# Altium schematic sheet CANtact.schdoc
size 366 x 256 mm
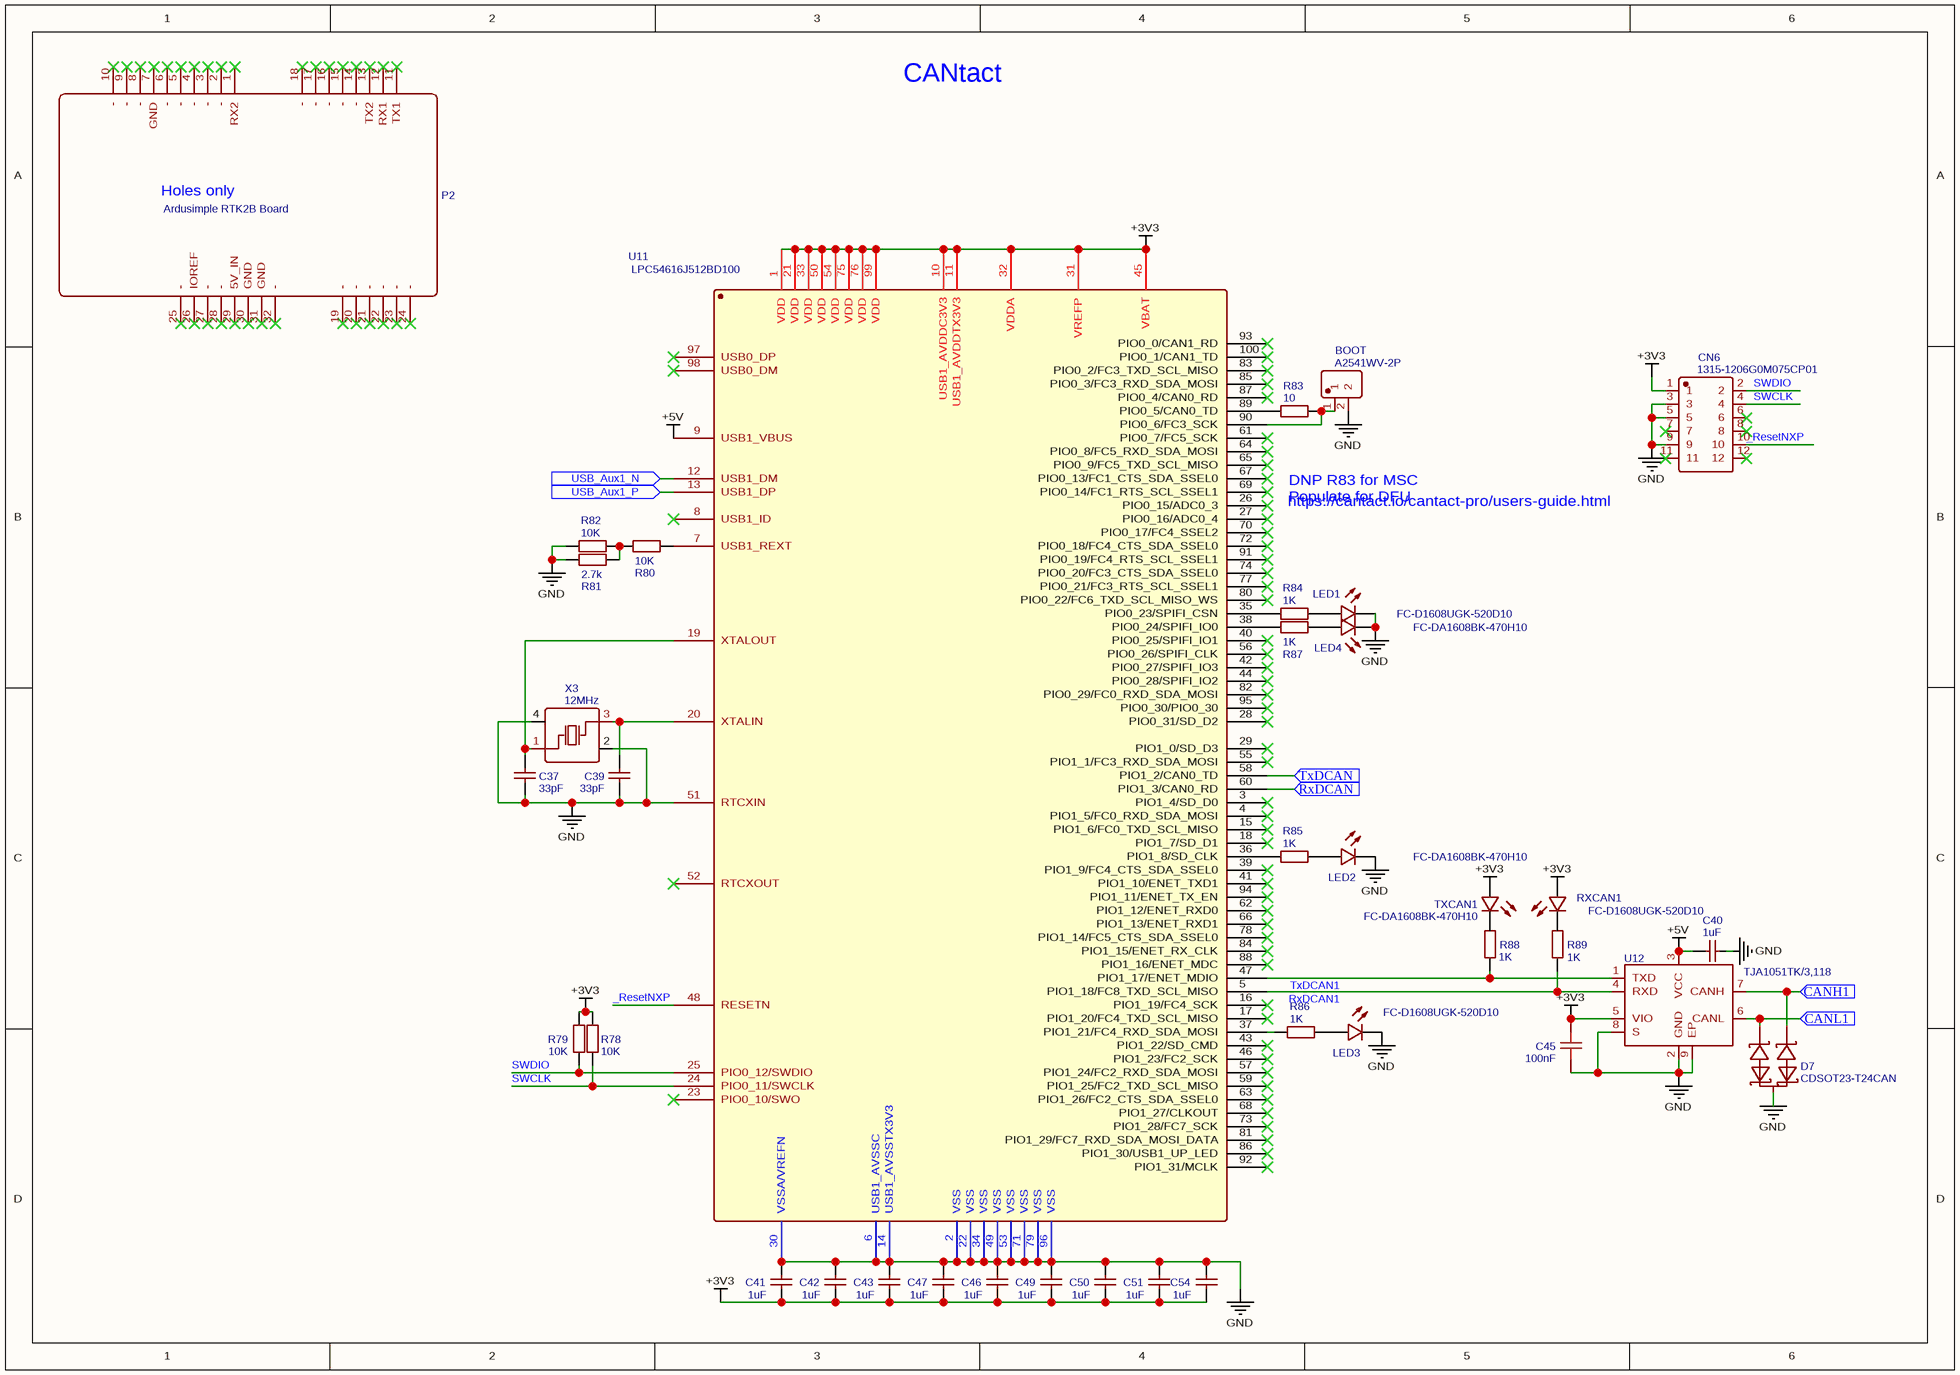
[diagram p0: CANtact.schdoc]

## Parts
BOOT  A2541WV-2P  [HDR-TH_P2.54-H-M_A2541WV-2P]
C37  33pF  [C0603]
C39  33pF  [C0603]
C40  1uF  [C0603]
C41  1uF  [C0603]
C42  1uF  [C0603]
C43  1uF  [C0603]
C45  100nF  [C0603]
C46  1uF  [C0603]
C47  1uF  [C0603]
C49  1uF  [C0603]
C50  1uF  [C0603]
C51  1uF  [C0603]
C54  1uF  [C0603]
CN6  1315-1206G0M075CP01  [HDR-SMD_12P-P1.27-V-M-R2-C6-S7.50]
D7  CDSOT23-T24CAN  [SOT-23_L2.9-W1.3-P0.95-LS2.4-BR]
LED1  FC-D1608UGK-520D10  [LED0603-RD]
LED2  FC-DA1608BK-470H10  [LED0603-RD]
LED3  FC-D1608UGK-520D10  [LED0603-RD]
LED4  FC-DA1608BK-470H10  [LED0603-RD]
P2  Ardusimple RTK2B Board  [ARDUSIMPLE_MECH]
R78  10K  [R0603]
R79  10K  [R0603]
R80  10K  [R0603]
R81  2.7k  [R0603]
R82  10K  [R0603]
R83  10  [R0603]
R84  1K  [R0603]
R85  1K  [R0603]
R86  1K  [R0603]
R87  1K  [R0603]
R88  1K  [R0603]
R89  1K  [R0603]
RXCAN1  FC-D1608UGK-520D10  [LED0603-RD]
TXCAN1  FC-DA1608BK-470H10  [LED0603-RD]
U11  LPC54616J512BD100  [TQFP-100_14X14X05P]
U12  TJA1051TK/3,118  [HVSON-8_L3.0-W3.0-P0.65-BL-EP]
X3  12MHz  [OSC-SMD_4P-L3.2-W2.5-BL]

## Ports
CANH1 (in), CANL1 (in), RxDCAN (in), TxDCAN (in), USB_Aux1_N (in), USB_Aux1_P (in)

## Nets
+3V3: C41.2 C42.2 C43.2 C45.2 C46.2 C47.2 C49.2 C50.2 C51.2 C54.2 CN6.1 R78.1 R79.1 RXCAN1.2(A) TXCAN1.2(+) U11.1(VDD) U11.10(USB1_AVDDC3V3) U11.11(USB1_AVDDTX3V3) U11.21(VDD) U11.31(VREFP) U11.32(VDDA) U11.33(VDD) U11.45(VBAT) U11.50(VDD) U11.54(VDD) U11.75(VDD) U11.76(VDD) U11.99(VDD) U12.5(VIO)
+5V: C40.1 U11.9(USB1_VBUS) U12.3(VCC)
GND: BOOT.2 C37.1 C39.1 C40.2 C41.1 C42.1 C43.1 C45.1 C46.1 C47.1 C49.1 C50.1 C51.1 C54.1 CN6.3 CN6.5 CN6.9 D7.3 LED1.1(K) LED2.1(-) LED3.1(K) LED4.1(-) R81.2 R82.2 U11.2(VSS) U11.6(USB1_AVSSC) U11.14(USB1_AVSSTX3V3) U11.22(VSS) U11.30(VSSA/VREFN) U11.34(VSS) U11.49(VSS) U11.51(RTCXIN) U11.53(VSS) U11.71(VSS) U11.79(VSS) U11.96(VSS) U12.2(GND) U12.8(S) U12.9(EP) X3.2(GND) X3.4(GND)
_ResetNXP: CN6.10 U11.48(RESETN)
CANH1: D7.1 U12.7(CANH) ; port CANH1
CANL1: D7.2 U12.6(CANL) ; port CANL1
RxDCAN: U11.60(PIO1_3/CAN0_RD) ; port RxDCAN
RxDCAN1: R89.2 U11.5(PIO1_18/FC8_TXD_SCL_MISO) U12.4(RXD)
SWCLK: CN6.4 R78.2 U11.24(PIO0_11/SWCLK)
SWDIO: CN6.2 R79.2 U11.25(PIO0_12/SWDIO)
TxDCAN: U11.58(PIO1_2/CAN0_TD) ; port TxDCAN
TxDCAN1: R88.2 U11.47(PIO1_17/ENET_MDIO) U12.1(TXD)
USB_Aux1_N: U11.12(USB1_DM) ; port USB_Aux1_N
USB_Aux1_P: U11.13(USB1_DP) ; port USB_Aux1_P
NetBOOT_1: BOOT.1 R83.1 U11.90(PIO0_6/FC3_SCK)
NetC37_2: C37.2 U11.19(XTALOUT) X3.1(OSC1)
NetC39_2: C39.2 U11.20(XTALIN) X3.3(OSC2)
NetLED1_2: LED1.2(A) R84.1
NetLED2_2: LED2.2(+) R85.1
NetLED3_2: LED3.2(A) R86.1
NetLED4_2: LED4.2(+) R87.1
NetR80_1: R80.1 U11.7(USB1_REXT)
NetR80_2: R80.2 R81.1 R82.1
NetR83_2: R83.2 U11.89(PIO0_5/CAN0_TD)
NetR84_2: R84.2 U11.35(PIO0_23/SPIFI_CSN)
NetR85_2: R85.2 U11.36(PIO1_8/SD_CLK)
NetR86_2: R86.2 U11.37(PIO1_21/FC4_RXD_SDA_MOSI)
NetR87_2: R87.2 U11.38(PIO0_24/SPIFI_IO0)
NetR88_1: R88.1 TXCAN1.1(-)
NetR89_1: R89.1 RXCAN1.1(K)

Not connected (* = marked no-connect by the designer): CN6 6* 7* 8* 11* 12*; P2 1(RX2)* 2(-)* 3(-)* 4(-)* 5(-)* 6(-)* 7(GND)* 8(-)* 9(-)* 10(-)* 11(TX1)* 12(RX1)* 13(TX2)* 14(-)* 15(-)* 16(-)* 17(-)* 18(-)* 19(-)* 20(-)* 21(-)* 22(-)* 23(-)* 24(-)* 25(-)* 26(IOREF)* 27(-)* 28(-)* 29(5V_IN)* 30(GND)* 31(GND)* 32(-)*; U11 3(PIO1_4/SD_D0)* 4(PIO1_5/FC0_RXD_SDA_MOSI)* 8(USB1_ID)* 15(PIO1_6/FC0_TXD_SCL_MISO)* 16(PIO1_19/FC4_SCK)* 17(PIO1_20/FC4_TXD_SCL_MISO)* 18(PIO1_7/SD_D1)* 23(PIO0_10/SWO)* 26(PIO0_15/ADC0_3)* 27(PIO0_16/ADC0_4)* 28(PIO0_31/SD_D2)* 29(PIO1_0/SD_D3)* 39(PIO1_9/FC4_CTS_SDA_SSEL0)* 40(PIO0_25/SPIFI_IO1)* 41(PIO1_10/ENET_TXD1)* 42(PIO0_27/SPIFI_IO3)* 43(PIO1_22/SD_CMD)* 44(PIO0_28/SPIFI_IO2)* 46(PIO1_23/FC2_SCK)* 52(RTCXOUT)* 55(PIO1_1/FC3_RXD_SDA_MOSI)* 56(PIO0_26/SPIFI_CLK)* 57(PIO1_24/FC2_RXD_SDA_MOSI)* 59(PIO1_25/FC2_TXD_SCL_MISO)* 61(PIO0_7/FC5_SCK)* 62(PIO1_12/ENET_RXD0)* 63(PIO1_26/FC2_CTS_SDA_SSEL0)* 64(PIO0_8/FC5_RXD_SDA_MOSI)* 65(PIO0_9/FC5_TXD_SCL_MISO)* 66(PIO1_13/ENET_RXD1)* 67(PIO0_13/FC1_CTS_SDA_SSEL0)* 68(PIO1_27/CLKOUT)* 69(PIO0_14/FC1_RTS_SCL_SSEL1)* 70(PIO0_17/FC4_SSEL2)* 72(PIO0_18/FC4_CTS_SDA_SSEL0)* 73(PIO1_28/FC7_SCK)* 74(PIO0_20/FC3_CTS_SDA_SSEL0)* 77(PIO0_21/FC3_RTS_SCL_SSEL1)* 78(PIO1_14/FC5_CTS_SDA_SSEL0)* 80(PIO0_22/FC6_TXD_SCL_MISO_WS)* 81(PIO1_29/FC7_RXD_SDA_MOSI_DATA)* 82(PIO0_29/FC0_RXD_SDA_MOSI)* 83(PIO0_2/FC3_TXD_SCL_MISO)* 84(PIO1_15/ENET_RX_CLK)* 85(PIO0_3/FC3_RXD_SDA_MOSI)* 86(PIO1_30/USB1_UP_LED)* 87(PIO0_4/CAN0_RD)* 88(PIO1_16/ENET_MDC)* 91(PIO0_19/FC4_RTS_SCL_SSEL1)* 92(PIO1_31/MCLK)* 93(PIO0_0/CAN1_RD)* 94(PIO1_11/ENET_TX_EN)* 95(PIO0_30/PIO0_30)* 97(USB0_DP)* 98(USB0_DM)* 100(PIO0_1/CAN1_TD)*

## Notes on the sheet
- CANtact
- DNP R83 for MSC
  Populate for DFU
- https://cantact.io/cantact-pro/users-guide.html

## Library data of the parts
BOOT = A2541WV-2P: BOM_Manufacturer: CJT(Changjiang Connectors); Contributor: LCSC
C37 C39 = 33pF: BOM_Manufacturer: SAMSUNG; BOM_Manufacturer Part: CL10C330JB8NNNC; nameAlias: Capacitance
C40-C43 C46 C47 C49-C51 C54 = 1uF: BOM_Manufacturer Part: CL10A105KP8NNNC; BOM_Manufacturer: SAMSUNG; nameAlias: Capacitance
C45 = 100nF: BOM_Manufacturer: YAGEO; BOM_Manufacturer Part: CC0603JRX7R8BB104; nameAlias: Capacitance; Contributor: LCSC
CN6 = 1315-1206G0M075CP01: BOM_Manufacturer: Wcon; Contributor: LCSC
D7 = CDSOT23-T24CAN: BOM_Manufacturer: Yenji Elec; Contributor: LCSC; SMT Type: Extend
LED1 LED3 RXCAN1 = FC-D1608UGK-520D10: BOM_Manufacturer: NATIONSTAR; SMT Type: Extend
LED2 LED4 TXCAN1 = FC-DA1608BK-470H10: BOM_Manufacturer: NATIONSTAR
P2 = Ardusimple RTK2B Board: sourceId: 1T5FDZYC8; Contributor: DiaZ0te
R78-R80 R82 = 10K: BOM_Manufacturer: RALEC; BOM_Manufacturer Part: RTT03103JTP; nameAlias: Resistance (Ohms)
R81 = 2.7k: BOM_Manufacturer: RALEC; BOM_Manufacturer Part: RTT03272JTP; nameAlias: Resistance (Ohms)
R83 = 10: BOM_Manufacturer: RALEC; BOM_Manufacturer Part: RTT03100JTP; nameAlias: Resistance (Ohms)
R84-R89 = 1K: BOM_Manufacturer: RALEC; BOM_Manufacturer Part: RTT03102JTP; nameAlias: Resistance (Ohms)
U11 = LPC54616J512BD100: Contributor: arkkar
U12 = TJA1051TK/3,118: BOM_Manufacturer: NXP
X3 = 12MHz: BOM_Manufacturer: YXC; BOM_Manufacturer Part: X322512MSB4SI; nameAlias: Frequency; SMT Type: Basic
